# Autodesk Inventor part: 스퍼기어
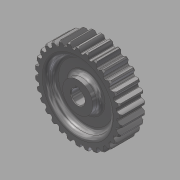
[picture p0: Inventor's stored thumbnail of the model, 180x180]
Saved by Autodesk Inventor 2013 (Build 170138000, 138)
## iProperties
Created: 2015-11
Part Number: 스퍼기어
Material: 강철, 탄소
Document SubType Name: Modeling
Designer: mduedu
Density: 1 g/cm^3
Author: mduedu
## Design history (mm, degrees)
sketch "스케치1"
  geometry: C1 r 28.75 at (0, 0); 1 further point
  constraints: 1 centre point, 1 coincident
  dimensions: "d0" = 57.5 diameter of C1
extrude "돌출1" new body sketch "스케치1" stored distance "d2" = 18; taper "d3" = 0 deg
sketch "스케치2" dims "d4" = 60
  geometry: L1 (0, 0)-(0, 32); L2 (-32, 0)-(32, 0); L3 (-2.07, 0)-(-2.07, 40.614); L4 (-2.07, 40.614)-(-1.57, 40.614); L5 (-1.57, 40.614)-(-1.57, 0); L6 (-0.57, 0)-(-0.57, 40.614); L7 (-0.57, 40.614)-(0, 40.614); L8 (0, 40.614)-(0, 0); A1 r 32 centre (0, 0) between (0.57, 31.995) and (-0.57, 31.995); A2 r 21.436 centre (18.143, 21.54) between (-0.57, 31.995) and (-2.07, 28.675); A3 r 21.436 centre (-18.143, 21.54) between (2.07, 28.675) and (0.57, 31.995); A4 r 32 centre (0, 0) between (32, 0) and (0.57, 31.995); A5 r 32 centre (0, 0) between (-0.57, 31.995) and (32, 0); A6 r 28.75 centre (0, 0) between (2.07, 28.675) and (-2.07, 28.675); 4 further points
  constraints: 17 point on circle, 16 end point, 6 centre point, 6 point on line, 5 perpendicular, 4 coincident, 3 symmetric about line, 2 collinear, 1 midpoint, 1 parallel, 1 vertical, 6 other
  dimensions: "d6" = 64 diameter of A1; "d7" = 0.5 distance between parallel lines of L5 L3; "d8" = 1 distance between parallel lines of L6 L5; "d9" = 40.61409 distance of L4.end L5.end; "d10" = 1.57 distance between parallel lines of L8 L5
extrude "돌출2" join sketch "스케치2" stored distance "d11" = 18; taper "d12" = 0 deg
fillet "모깎기1" dims "d16" = 0.5
chamfer "모따기3" distance "d26" = 1; stored, may be unused: second distance "d27" = 2, angle "d28" = 45 deg
sketch "스케치3"
  geometry: C1 r 23 at (0, 0); C2 r 11 at (0, 0); 1 further point
  constraints: 2 centre point, 2 coincident
  dimensions: "d32" = 46 diameter of C1; "d33" = 22 diameter of C2
extrude "돌출3" cut sketch "스케치3" distance "d34" = 6; taper "d35" = 0 deg
fillet "모깎기2" dims "d36" = 3
hole "구멍1" diameter "d39" = 10; stored, may be unused: countersink angle "d43" = 90 deg, drill point angle "d45" = 118 deg; dims "d37" = 10, "d38" = 10, "d40" = 6, "d41" = 4, "d42" = 2, "d44" = 8
sketch "스케치5"
  geometry: L1 (-1.5, 0)-(1.5, 0); L2 (1.5, 0)-(1.5, 6.4); L3 (1.5, 6.4)-(-1.5, 6.4); L4 (-1.5, 6.4)-(-1.5, 0); 2 further points
  constraints: 8 end point, 2 parallel, 1 coincident, 1 horizontal, 1 midpoint, 1 perpendicular
  dimensions: "d46" = 3 distance of L2.end L3.end; "d48" = 6.4 distance of L1.end L2.end
extrude "돌출4" cut sketch "스케치5" stored distance "d49" = 6; taper "d50" = 0 deg
chamfer "모따기4" distance "d51" = 0.5; stored, may be unused: second distance "d52" = 2, angle "d53" = 45 deg
node "솔리드1"
pattern_circular "원형 패턴3" dims "d30" = 360 deg
mirror "대칭1"
